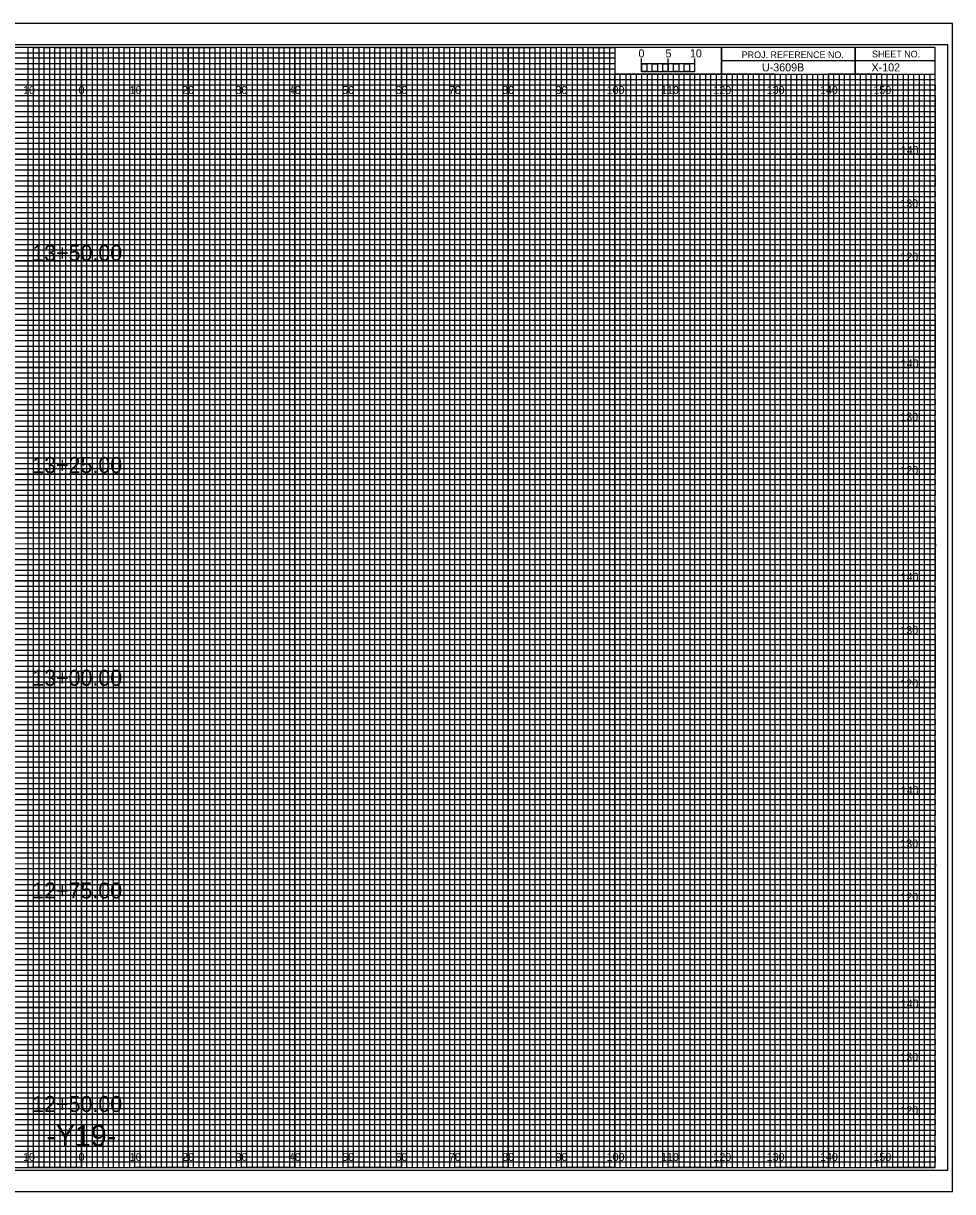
# Model space of a CAD drawing. Extents: x -13 to 323, y -5 to 654.
# Drawn here: x 149.1 to 323.3, y 435.5 to 654.5 of the extents above; entities that cross this region are included whole.
import ezdxf

# ---------------------------------------------------------------- set-up
doc = ezdxf.new("R2010")
doc.units = 0
for name, color, linetype in [('Prop XS Alignment Label', 7, 'Continuous'), ('Prop XS Bar Scale Labels', 7, 'Continuous'), ('Prop XS Elevation Labels', 7, 'Continuous'), ('Prop XS Offset Labels', 7, 'Continuous'), ('Prop XS Project Number', 7, 'Continuous'), ('Prop XS Sheet Number', 7, 'Continuous'), ('Prop XS Station Labels', 7, 'Continuous'), ('Sheet Cross Section CELL', 7, 'Continuous'), ('Sheet Cross Section Grid Major CELL', 7, 'Continuous'), ('Sheet Cross Section Grid Middle CELL', 7, 'Continuous'), ('Sheet Cross Section Grid Minor 1 CELL', 7, 'Continuous'), ('Sheet Cross Section Grid Minor 2 CELL', 7, 'Continuous'), ('Sheet Cross Section Scale CELL', 7, 'Continuous'), ('Sheet Cutting Line CELL', 7, 'Continuous'), ('Sheet DOT Grid CELL', 7, 'Continuous'), ('Sheet Plot Border Inside CELL', 7, 'Continuous'), ('Sheet Plot Border Outside CELL', 7, 'Continuous')]:
    doc.layers.add(name, color=color, linetype=linetype)

msp = doc.modelspace()

# ---------------------------------------------------------------- linework, layer by layer
at = {"layer": 'Sheet Cross Section CELL'}
for p, q in [((305, 650), (305, 645)), ((305, 645), (305, 650)), ((280, 647.5), (280, 645)), ((320, 647.49), (280, 647.49)), ((280, 645), (320, 645))]:
    msp.add_line(p, q, dxfattribs=at)
for points in [[(320, 650), (0, 650), (0, 440), (320, 440)], [(280, 650), (260, 650), (260, 645.03), (280, 645.03)], [(320, 650), (280, 650), (280, 645), (320, 645)]]:
    msp.add_lwpolyline(points, close=True, dxfattribs=at)
at = {"layer": 'Sheet Cross Section Grid Major CELL'}
for p, q in [((150, 650), (140, 650)), ((150, 440), (150, 650)), ((170, 650), (160, 650)), ((160, 650), (160, 440)), ((170, 440), (170, 650)), ((190, 650), (180, 650)), ((180, 650), (180, 440)), ((190, 440), (190, 650)), ((210, 650), (200, 650)), ((200, 650), (200, 440)), ((210, 440), (210, 650)), ((230, 650), (220, 650)), ((220, 650), (220, 440)), ((230, 440), (230, 650)), ((250, 650), (240, 650)), ((240, 650), (240, 440)), ((250, 440), (250, 650)), ((260, 650), (260, 440)), ((270, 440), (270, 645)), ((290, 645), (280, 645)), ((280, 645), (280, 440)), ((290, 440), (290, 645)), ((310, 645), (300, 645)), ((300, 645), (300, 440)), ((310, 440), (310, 645)), ((160, 440), (150, 440)), ((180, 440), (170, 440)), ((200, 440), (190, 440)), ((220, 440), (210, 440)), ((240, 440), (230, 440)), ((260, 440), (250, 440)), ((280, 440), (270, 440)), ((300, 440), (290, 440)), ((320, 440), (310, 440)), ((320, 440), (320, 440))]:
    msp.add_line(p, q, dxfattribs=at)
for points in [[(0, 640), (320, 640), (320, 630), (0, 630)], [(0, 620), (320, 620), (320, 610), (0, 610)], [(0, 600), (320, 600), (320, 590), (0, 590)], [(0, 580), (320, 580), (320, 570), (0, 570)], [(0, 560), (320, 560), (320, 550), (0, 550)], [(0, 540), (320, 540), (320, 530), (0, 530)], [(0, 520), (320, 520), (320, 510), (0, 510)], [(0, 500), (320, 500), (320, 490), (0, 490)], [(0, 480), (320, 480), (320, 470), (0, 470)], [(0, 460), (320, 460), (320, 450), (0, 450)]]:
    msp.add_lwpolyline(points, dxfattribs=at)
at = {"layer": 'Sheet Cross Section Grid Middle CELL'}
for points in [[(145, 440), (155, 440), (155, 650), (165, 650), (165, 440), (175, 440), (175, 650), (185, 650), (185, 440), (195, 440), (195, 650), (205, 650), (205, 440), (215, 440), (215, 650), (225, 650), (225, 440), (235, 440), (235, 650), (245, 650), (245, 440), (255, 440), (255, 650), (259.93, 650), (260, 650), (260, 645), (264.99, 645), (264.99, 440), (275, 440), (275, 645), (285, 645), (285, 440), (295, 440), (295, 645), (305, 645), (305, 440), (315, 440), (315, 645)], [(0, 645), (275, 645)], [(0, 625), (320, 625), (320, 635), (0, 635)], [(0, 605), (320, 605), (320, 615), (0, 615)], [(0, 585), (320, 585), (320, 595), (0, 595)], [(0, 565), (320, 565), (320, 575), (0, 575)], [(0, 545), (320, 545), (320, 555), (0, 555)], [(0, 525), (320, 525), (320, 535), (0, 535)], [(0, 505), (320, 505), (320, 515), (0, 515)], [(0, 485), (320, 485), (320, 495), (0, 495)], [(0, 465), (320, 465), (320, 475), (0, 475)], [(0, 445), (320, 445), (320, 455), (0, 455)]]:
    msp.add_lwpolyline(points, dxfattribs=at)
at = {"layer": 'Sheet Cross Section Grid Minor 1 CELL'}
for p, q in [((0, 649), (260, 649)), ((260, 649), (260, 647.98)), ((260, 647.98), (0, 647.98)), ((0, 647), (260, 647)), ((260, 647), (260, 645.89)), ((260, 645.89), (0, 645.89)), ((0, 644), (320, 644))]:
    msp.add_line(p, q, dxfattribs=at)
for points in [[(0, 643), (270, 643), (320, 643), (320, 642), (0, 642)], [(0, 641), (320, 641), (320, 639), (0, 639)], [(0, 638), (320, 638), (320, 637), (0, 636.98)], [(0, 636), (320, 636), (320, 634), (0, 634)], [(0, 633), (320, 633), (320, 632), (0, 632)], [(0, 631), (320, 631), (320, 629), (0, 629)], [(0, 628), (320, 628), (320, 627), (0, 627)], [(0, 626), (320, 626), (320, 624), (0, 624)], [(0, 623), (320, 623), (320, 622), (0, 622)], [(0, 621), (320, 621), (320, 619), (0, 619)], [(0, 618), (320, 618), (320, 617), (0, 617)], [(0, 616), (320, 616), (320, 613.95), (320, 613), (320, 612), (0, 612)], [(0, 614), (320, 614), (320, 613), (0, 613)], [(0, 611), (320, 611), (320, 609), (0, 609.03)], [(0, 609.03), (320, 609), (320, 608), (0, 608)], [(0, 607), (320, 607), (320, 606), (0, 606)], [(0, 604), (320, 604), (320, 603), (0, 603)], [(0, 602), (320, 602), (320, 601), (0, 601)], [(-0.07, 598.89), (320, 598.89), (320, 597.88), (-0.07, 597.88)], [(0, 597), (320, 597), (320, 596), (0, 596)], [(0, 594), (320, 594), (320, 593), (0, 593)], [(0, 592), (320, 592), (320, 591), (0, 591)], [(0, 589), (320, 589), (320, 588), (0, 588)], [(0, 587), (320, 587), (320, 586), (0, 586)], [(0, 584), (320, 584), (320, 583), (0, 583)], [(0, 582), (320, 582), (320, 581), (0, 581)], [(0, 579), (320, 579), (319.99, 577.98), (0, 578)], [(0, 577), (320, 577), (320, 576), (0, 576)], [(0, 574), (320, 574), (320, 573), (0, 573)], [(0, 572), (320, 572), (320, 571), (0, 571)], [(0, 569), (320, 569), (320, 568), (0, 568)], [(0, 567), (320, 567), (320, 566), (0, 566)], [(0, 564), (320, 564), (320, 563), (0, 563)], [(0, 562), (320, 562), (320, 561), (0, 561)], [(0, 559), (320, 559), (320, 558), (0, 558)], [(0, 556.99), (320.07, 556.91), (320, 556), (0, 556)], [(0, 554), (320, 554), (320, 553), (0, 553)], [(0, 552), (320, 552), (320, 551), (0, 551)], [(0, 549), (320, 549), (320, 548), (0, 548)], [(0, 547), (320, 547), (320, 546), (0, 546)], [(0, 544), (320, 544), (320, 543), (0, 543)], [(0, 542), (320, 542), (320, 541), (0, 541)], [(0, 539), (320, 539), (320, 538), (0, 538)], [(0, 537), (320, 537), (320, 536), (0, 536)], [(0, 534), (320, 534), (320, 533), (0, 533)], [(0, 532), (320, 532), (320, 531), (0, 531)], [(0, 529), (320, 529), (320, 528), (0, 528)], [(0, 527), (320, 527), (320, 526), (0, 526)], [(0, 524), (320, 524), (320, 523), (0, 523)], [(0, 522), (320, 522), (320, 521), (0, 521)], [(0, 519), (320, 519), (319.99, 517.98), (0, 518)], [(0, 517), (320, 517), (320, 516), (0, 516)], [(0, 514), (320, 514), (320, 513), (0, 513)], [(0, 512), (320, 512), (320, 511), (0, 511)], [(0, 509), (320, 509), (320, 508), (0, 508)], [(0, 507), (320, 507), (320, 506), (0, 506)], [(0, 504), (320, 504), (320, 503), (0, 503)], [(0, 502), (320, 502), (320, 501), (0, 501)], [(0, 499), (320, 499), (320, 498), (0, 498)], [(0, 496.99), (320.07, 496.91), (320, 496), (0, 496)], [(0, 494), (320, 494), (320, 493), (0, 493)], [(0, 492), (320, 492), (320, 491), (0, 491)], [(0, 489), (320, 489), (320, 488), (0, 488)], [(0, 487), (320, 487), (320, 486), (0, 486)], [(0, 484), (320, 484), (320, 483), (0, 483)], [(0, 482), (320, 482), (320, 481), (0, 481)], [(0, 479), (320, 479), (320, 478), (0, 478)], [(0, 477), (320, 477), (320, 476), (0, 476)], [(0, 474), (320, 474), (320, 473), (0, 473)], [(0, 472), (320, 472), (320, 471), (0, 471)], [(0, 469), (320, 469), (320, 468), (0, 468)], [(0, 467), (320, 467), (320, 466), (0, 466)], [(0, 464), (320, 464), (320, 463), (0, 463)], [(0, 462), (320, 462), (320, 461), (0, 461)], [(0, 459), (320, 459), (320, 458), (0, 458)], [(0, 457), (320, 457), (320, 456), (0, 456)], [(0, 454), (320, 454), (320, 453), (0, 453)], [(0, 452), (320, 452), (320, 451), (0, 451)], [(0, 449), (320, 449), (320, 448), (0, 448)], [(0, 447), (320, 447), (320, 446), (0, 446)], [(0, 444), (320, 444), (320, 443), (0, 443)], [(0, 442), (320, 442), (320, 441), (0, 441)]]:
    msp.add_lwpolyline(points, dxfattribs=at)
at = {"layer": 'Sheet Cross Section Grid Minor 2 CELL'}
for p, q in [((267, 645), (266.01, 645)), ((266.01, 645), (266.01, 440)), ((267, 440), (267, 645)), ((269, 645), (268, 645)), ((268, 645), (268, 440)), ((269, 440), (269, 645)), ((266.01, 440), (265, 440)), ((268, 440), (267, 440))]:
    msp.add_line(p, q, dxfattribs=at)
for points in [[(150, 440), (151, 440), (151, 650), (152, 650), (152, 440)], [(152, 440), (153, 440), (153, 650), (154, 650), (154, 440)], [(155, 440), (156, 440), (156, 650), (157, 650), (157, 440)], [(157, 440), (158, 440), (158, 650), (159, 650), (159, 440)], [(160, 440), (161, 440), (161, 650), (162, 650), (162, 440)], [(162, 440), (163, 440), (163, 650), (164, 650), (164, 440)], [(165, 440), (166, 440), (166, 650), (167, 650), (167, 440)], [(167, 440), (168, 440), (168, 650), (169, 650), (169, 440)], [(170, 440), (171, 440), (171, 650), (172, 650), (172, 440)], [(172, 440), (173, 440), (173, 650), (174, 650), (174, 440)], [(175, 440), (176, 440), (176, 650), (177, 650), (177, 440)], [(177, 440), (178, 440), (178, 650), (179, 650), (179, 440)], [(180, 440), (181, 440), (181, 650), (182, 650), (182, 440)], [(182, 440), (183, 440), (183, 650), (184, 650), (184, 440)], [(185, 440), (186, 440), (186, 650), (187, 650), (187, 440)], [(187, 440), (188, 440), (188, 650), (189, 650), (189, 440)], [(190, 440), (191, 440), (191, 650), (192, 650), (192, 440)], [(192, 440), (193, 440), (193, 650), (194, 650), (194, 440)], [(195, 440), (196, 440), (196, 650), (197, 650), (197, 440)], [(197, 440), (198, 440), (198, 650), (199, 650), (199, 440)], [(200, 440), (201, 440), (201, 650), (202, 650), (202, 440)], [(202, 440), (203, 440), (203, 650), (204, 650), (204, 440)], [(205, 440), (206, 440), (206, 650), (207, 650), (207, 440)], [(207, 440), (208, 440), (208, 650), (209, 650), (209, 440)], [(210, 440), (211, 440), (211, 650), (212, 650), (212, 440)], [(212, 440), (213, 440), (213, 650), (214, 650), (214, 440)], [(215, 440), (216, 440), (216, 650), (217, 650), (217, 440)], [(217, 440), (218, 440), (218, 650), (219, 650), (219, 440)], [(220, 440), (221, 440), (221, 650), (222, 650), (222, 440)], [(222, 440), (223, 440), (223, 650), (224, 650), (224, 440)], [(225, 440), (226, 440), (226, 650), (227, 650), (227, 440)], [(227, 440), (228, 440), (228, 650), (229, 650), (229, 440)], [(230, 440), (231, 440), (231, 650), (232, 650), (232, 440)], [(232, 440), (233, 440), (233, 650), (234, 650), (234, 440)], [(235, 440), (236, 440), (236, 650), (237, 650), (237, 440)], [(237, 440), (238, 440), (238, 650), (239, 650), (239, 440)], [(240, 440), (241, 440), (241, 650), (242, 650), (242, 440)], [(242, 440), (243, 440), (243, 650), (244, 650), (244, 440)], [(245, 440), (246, 440), (246, 650), (247, 650), (247, 440)], [(247, 440), (248, 440), (248, 650), (249, 650), (249, 440)], [(250, 440), (251, 440), (251, 650), (252, 650), (252, 440)], [(252, 440), (253, 440), (253, 650), (254, 650), (254, 440)], [(255, 440), (256, 440), (256, 650), (257, 650), (257, 440)], [(257, 440), (258, 440), (258, 650), (259, 650), (259, 440)], [(260, 440), (261, 440), (261, 645), (262.02, 645), (262.02, 440)], [(262, 440), (263, 440), (263, 645), (263.99, 645), (263.99, 440)], [(270, 440), (270.98, 440), (270.98, 645), (272, 645), (272, 440)], [(272, 440), (273, 440), (273, 645), (274.05, 645), (274.05, 440)], [(275, 440), (276, 440), (276, 645), (277, 645), (277, 440)], [(277, 440), (278, 440), (278, 645), (279, 645), (279, 440)], [(280, 440), (281, 440), (281, 645), (282, 645), (282, 440)], [(282, 440), (283, 440), (283, 645), (284, 645), (284, 440)], [(285, 440), (286, 440), (286, 645), (287, 645), (287, 440)], [(287, 440), (288, 440), (288, 645), (289, 645), (289, 440)], [(290, 440), (291, 440), (291, 645), (292, 645), (292, 440)], [(292, 440), (293, 440), (293, 645), (294, 645), (294, 440)], [(295, 440), (296, 440), (296, 645), (297, 645), (297, 440)], [(297, 440), (298, 440), (298, 645), (299, 645), (299, 440)], [(300, 440), (301, 440), (301, 645), (302, 645), (302, 440)], [(302, 440), (303, 440), (303, 645), (304, 645), (304, 440)], [(305, 440), (306, 440), (306, 645), (307, 645), (307, 440)], [(307, 440), (308, 440), (308, 645), (309, 645), (309, 440)], [(310, 440), (311, 440), (311, 645), (312, 645), (312, 440)], [(312, 440), (313, 440), (313, 645), (314, 645), (314, 440)], [(315, 440), (316, 440), (316, 645), (317, 645), (317, 440)], [(317, 440), (318, 440), (318, 645), (319, 645), (319, 440)]]:
    msp.add_lwpolyline(points, dxfattribs=at)
at = {"layer": 'Sheet Cross Section Scale CELL'}
for p, q in [((265, 645.49), (265, 647.9)), ((265, 646.9), (265, 647.9)), ((270, 645.49), (270, 647.9)), ((275, 645.49), (275, 647.9)), ((275, 646.9), (275, 647.9))]:
    msp.add_line(p, q, dxfattribs=at)
for points in [[(275, 646.9), (265, 646.9), (265, 645.49), (275, 645.49)], [(265, 646.9), (266, 646.9), (266, 645.49), (265, 645.49)], [(267, 646.9), (268, 646.9), (268, 645.49), (267, 645.49)], [(269, 646.9), (270, 646.9), (270, 645.49), (269, 645.49)], [(271, 646.9), (272, 646.9), (272, 645.49), (271, 645.49)], [(273, 646.9), (274, 646.9), (274, 645.49), (273, 645.49)]]:
    msp.add_lwpolyline(points, close=True, dxfattribs=at)
at = {"layer": 'Sheet Cutting Line CELL'}
for p, q in [((323.3, 654.5), (-13.4, 654.5)), ((-13.4, 435.5), (323.3, 435.5))]:
    msp.add_line(p, q, dxfattribs=at)
at = {"layer": 'Sheet DOT Grid CELL'}
for p, q in [((150, 440), (150, 650)), ((160, 440), (160, 650)), ((170, 440), (170, 650)), ((180, 440), (180, 650)), ((190, 440), (190, 650)), ((200, 440), (200, 650)), ((210, 440), (210, 650)), ((220, 440), (220, 650)), ((230, 440), (230, 650)), ((240, 440), (240, 650)), ((250, 440), (250, 650)), ((260, 440), (260, 644.69)), ((270, 440), (270, 644.69)), ((280, 440), (280, 644.69)), ((290, 440), (290, 644.69)), ((300, 440), (300, 644.69)), ((310, 440), (310, 644.69)), ((0, 640), (320, 640)), ((0, 630), (320, 630)), ((0, 620), (320, 620)), ((0, 610), (320, 610)), ((0, 600), (320, 600)), ((0, 590), (320, 590)), ((0, 580), (320, 580)), ((0, 570), (320, 570)), ((0, 560), (320, 560)), ((0, 550), (320, 550)), ((0, 540), (320, 540)), ((0, 530), (320, 530)), ((0, 520), (320, 520)), ((0, 510), (320, 510)), ((0, 500), (320, 500)), ((0, 490), (320, 490)), ((0, 480), (320, 480)), ((0, 470), (320, 470)), ((0, 460), (320, 460)), ((0, 450), (320, 450))]:
    msp.add_line(p, q, dxfattribs=at)
at = {"layer": 'Sheet Plot Border Inside CELL'}
msp.add_lwpolyline([(-10.8, 439.5), (322.4, 439.5), (322.4, 650.5), (-10.8, 650.5)], close=True, dxfattribs=at)
at = {"layer": 'Sheet Plot Border Outside CELL'}
msp.add_lwpolyline([(-13.4, 435.5), (323.3, 435.5), (323.3, 654.5), (-13.4, 654.5)], close=True, dxfattribs=at)

# ---------------------------------------------------------------- texts
at = {"layer": 'Prop XS Alignment Label'}
msp.add_text('-Y19-', height=4, dxfattribs=at).set_placement((153.41, 444))
at = {"layer": 'Prop XS Bar Scale Labels'}
for s, p in [('5', (269.47, 648.12)), ('10', (274.04, 648.12))]:
    msp.add_text(s, height=1.5, dxfattribs=at).set_placement(p)
at = {"layer": 'Prop XS Elevation Labels'}
for s, p in [('140', (313.57, 630)), ('130', (313.49, 620)), ('120', (313.5, 610)), ('140', (313.57, 590)), ('130', (313.49, 580)), ('120', (313.5, 570)), ('140', (313.57, 550)), ('130', (313.49, 540)), ('120', (313.5, 530)), ('140', (313.57, 510)), ('130', (313.49, 500)), ('120', (313.5, 490)), ('140', (313.57, 470)), ('130', (313.49, 460)), ('120', (313.5, 450))]:
    msp.add_text(s, height=1.5, dxfattribs=at).set_placement(p)
at = {"layer": 'Prop XS Offset Labels'}
for s, p in [('10', (149.04, 641.25)), ('0', (159.45, 641.25)), ('0', (159.45, 641.25)), ('10', (169.04, 641.25)), ('20', (178.86, 641.25)), ('30', (188.86, 641.25)), ('40', (198.86, 641.25)), ('50', (208.86, 641.25)), ('60', (218.86, 641.25)), ('70', (228.86, 641.25)), ('80', (238.86, 641.25)), ('90', (248.86, 641.25)), ('100', (258.44, 641.25)), ('110', (268.62, 641.25)), ('120', (278.44, 641.25)), ('130', (288.44, 641.25)), ('140', (298.44, 641.25)), ('150', (308.44, 641.25)), ('10', (149.04, 441.25)), ('0', (159.45, 441.25)), ('0', (159.45, 441.25)), ('10', (169.04, 441.25)), ('20', (178.86, 441.25)), ('30', (188.86, 441.25)), ('40', (198.86, 441.25)), ('50', (208.86, 441.25)), ('60', (218.86, 441.25)), ('70', (228.86, 441.25)), ('80', (238.86, 441.25)), ('90', (248.86, 441.25)), ('100', (258.44, 441.25)), ('110', (268.62, 441.25)), ('120', (278.44, 441.25)), ('130', (288.44, 441.25)), ('140', (298.44, 441.25)), ('150', (308.44, 441.25))]:
    msp.add_text(s, height=1.5, dxfattribs=at).set_placement(p)
at = {"layer": 'Prop XS Project Number'}
msp.add_text('U-3609B', height=1.5, dxfattribs=at).set_placement((287.56, 645.5))
at = {"layer": 'Prop XS Sheet Number'}
msp.add_text('X-102', height=1.5, dxfattribs=at).set_placement((308.09, 645.5))
at = {"layer": 'Prop XS Station Labels'}
for s, p in [('13+50.00', (150.77, 609.97)), ('13+25.00', (150.77, 570.21)), ('13+00.00', (150.77, 530.33)), ('12+75.00', (150.77, 490.46)), ('12+50.00', (150.77, 450.43))]:
    msp.add_text(s, height=3, dxfattribs=at).set_placement(p)
at = {"layer": 'Sheet Cross Section CELL'}
for s, p in [('PROJ. REFERENCE NO.', (283.77, 647.99)), ('SHEET NO.', (308.19, 648.12))]:
    msp.add_text(s, height=1.25, dxfattribs=at).set_placement(p)
at = {"layer": 'Sheet Cross Section Scale CELL'}
msp.add_text('0', height=1.5, dxfattribs=at).set_placement((264.41, 648.12))

doc.saveas('drawing.dxf')
